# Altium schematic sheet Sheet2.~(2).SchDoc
size A3
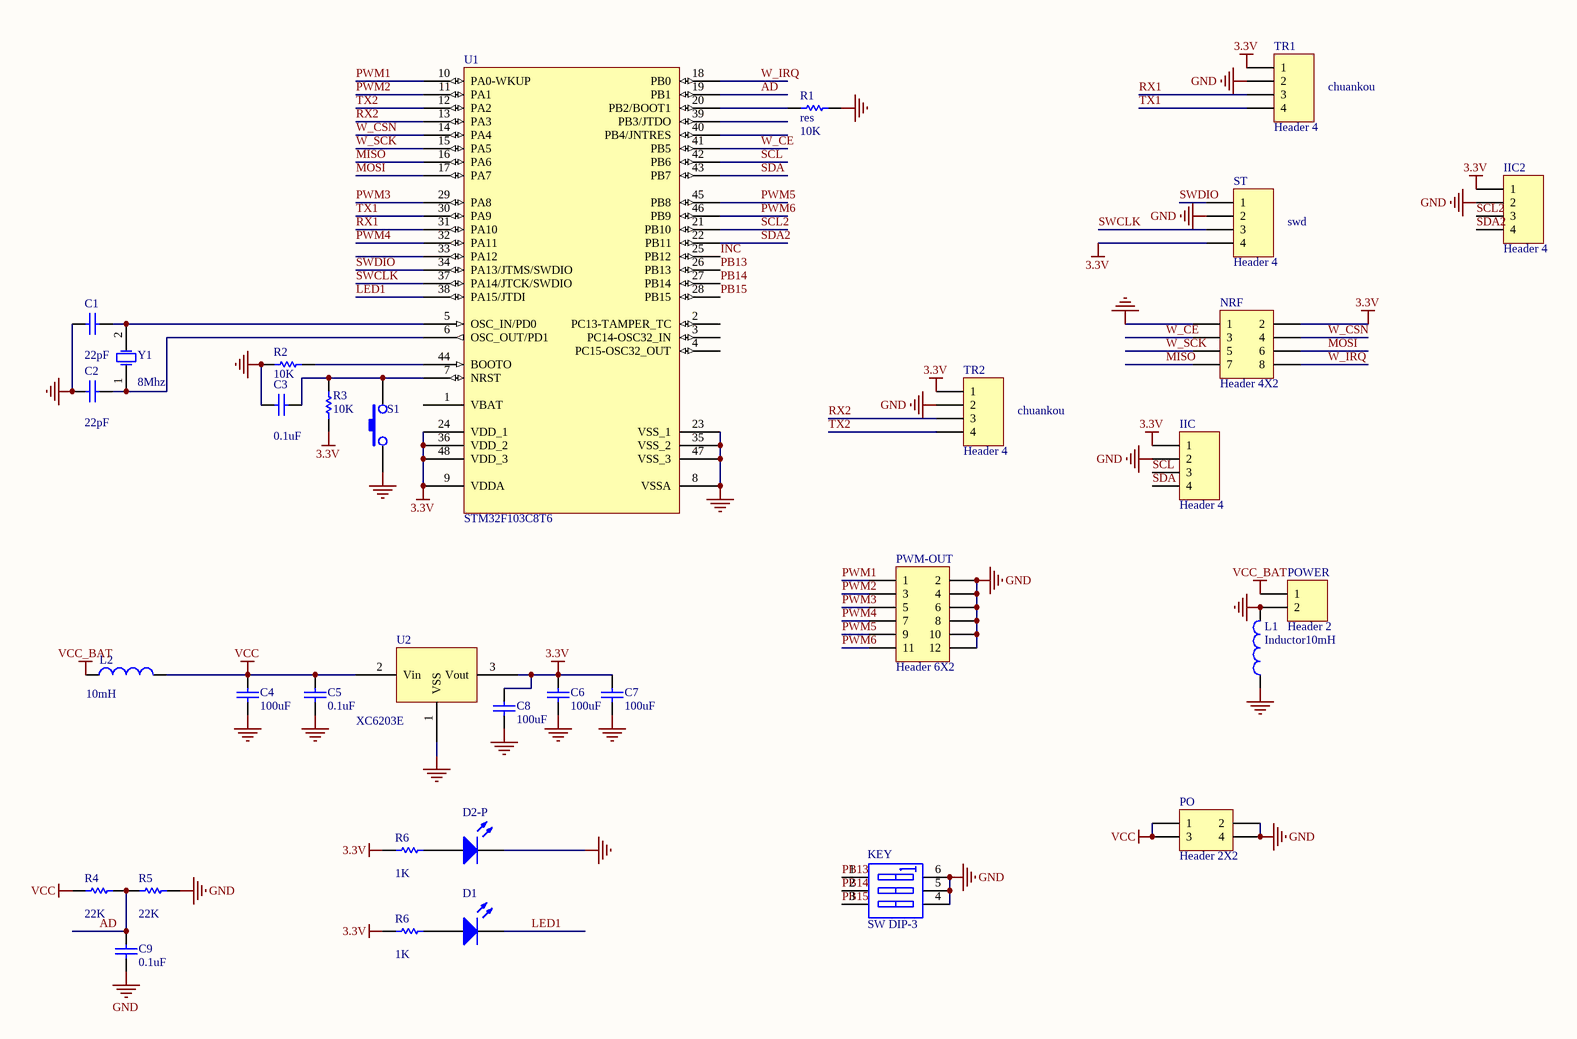
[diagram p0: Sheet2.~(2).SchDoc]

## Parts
(Parts that share a designator on the sheet are numbered #1, #2 ... from top to bottom, then left to right.)
C1  value 22pF  [0603]  (hidden comment: cap)
C2  value 22pF  [0603]  (hidden comment: cap)
C3  value 0.1uF  [0603]  (hidden comment: cap)
C4  value 100uF  [0603]  (hidden comment: cap)
C5  value 0.1uF  [0603]  (hidden comment: cap)
C6  value 100uF  [0603]  (hidden comment: cap)
C7  value 100uF  [0603]  (hidden comment: cap)
C8  value 100uF  [0603]  (hidden comment: cap)
C9  value 0.1uF  [0603]  (hidden comment: cap)
D1  LED0  [0805]  (value not drawn)
D2-P  LED0  [0805]  (value not drawn)
IIC  Header 4  [HDR1X4]
IIC2  Header 4  [HDR1X4]
KEY  SW DIP-3
L1  Inductor10mH  [0805]
L2  value 10mH  [0805]  (hidden comment: Inductor)
NRF  Header 4X2  [HDR2X4]
PO  Header 2X2  [HDR2X2]
POWER  Header 2  [HDR1X2]
PWM-OUT  Header 6X2  [HDR2X6]
R1  res  res: 10K  [0603]
R2  res: 10K  [0603]  (hidden comment: res)
R3  res: 10K  [0603]  (hidden comment: res)
R4  res: 22K  [0603]  (hidden comment: res)
R5  res: 22K  [0603]  (hidden comment: res)
R6#1  res: 1K  [0603]  (hidden comment: res)
R6#2  res: 1K  [0603]  (hidden comment: res)
S1  (no value)
ST  Header 4  [HDR1X4]
TR1  Header 4  [HDR1X4]
TR2  Header 4  [HDR1X4]
U1  STM32F103C8T6  [LQFP48S]
U2  XC6203E  [SOT-89]
Y1  5032xtal  [XTAL]  (value not drawn)

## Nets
3.3V: C6.2 C7.2 C8.2 IIC.1 IIC2.1 NRF.2 R3.1 R6#1.1 R6#2.1 ST.4 TR1.1 TR2.1 U1.9(VDDA) U1.24(VDD_1) U1.36(VDD_2) U1.48(VDD_3) U2.3(Vout)
GND: C1.1 C2.1 C3.1 C4.1 C5.1 C6.1 C7.1 C8.1 C9.1 D2-P.2(K) IIC.2 IIC2.2 KEY.4(B3) KEY.5(B2) KEY.6(B1) L1.1 L1.2 NRF.1 PO.2 PO.4 POWER.2 PWM-OUT.2 PWM-OUT.4 PWM-OUT.6 PWM-OUT.8 PWM-OUT.10 PWM-OUT.12 R1.2 R2.1 R5.2 S1.1 ST.2 TR1.2 TR2.2 U1.8(VSSA) U1.23(VSS_1) U1.35(VSS_2) U1.47(VSS_3) U2.1(VSS)
VCC: C4.2 C5.2 L2.2 PO.1 PO.3 R4.1 U2.2(Vin)
VCC_BAT: L2.1 POWER.1
AD: C9.2 R4.2 R5.1 U1.19(PB1)
INC: U1.25(PB12)
LED1: D1.2(K) U1.38(PA15/JTDI)
MISO: NRF.7 U1.16(PA6)
MOSI: NRF.6 U1.17(PA7)
PB13: KEY.1(A1) U1.26(PB13)
PB14: KEY.2(A2) U1.27(PB14)
PB15: KEY.3(A3) U1.28(PB15)
PWM1: PWM-OUT.1 U1.10(PA0-WKUP)
PWM2: PWM-OUT.3 U1.11(PA1)
PWM3: PWM-OUT.5 U1.29(PA8)
PWM4: PWM-OUT.7 U1.32(PA11)
PWM5: PWM-OUT.9 U1.45(PB8)
PWM6: PWM-OUT.11 U1.46(PB9)
RX1: TR1.3 U1.31(PA10)
RX2: TR2.3 U1.13(PA3)
SCL: IIC.3 U1.42(PB6)
SCL2: IIC2.3 U1.21(PB10)
SDA: IIC.4 U1.43(PB7)
SDA2: IIC2.4 U1.22(PB11)
SWCLK: ST.3 U1.37(PA14/JTCK/SWDIO)
SWDIO: ST.1 U1.34(PA13/JTMS/SWDIO)
TX1: TR1.4 U1.30(PA9)
TX2: TR2.4 U1.12(PA2)
W_CE: NRF.3 U1.41(PB5)
W_CSN: NRF.4 U1.14(PA4)
W_IRQ: NRF.8 U1.18(PB0)
W_SCK: NRF.5 U1.15(PA5)
NetC1_2: C1.2 U1.5(OSC_IN/PD0) Y1.2(OSC2)
NetC2_2: C2.2 U1.6(OSC_OUT/PD1) Y1.1(OSC1)
NetC3_2: C3.2 R3.2 S1.2 U1.7(NRST)
NetD1_1: D1.1(A) R6#2.2
NetD2-P_1: D2-P.1(A) R6#1.2
NetR1_1: R1.1 U1.20(PB2/BOOT1)
NetR2_2: R2.2 U1.44(BOOTO)

Not connected (* = marked no-connect by the designer): U1 1(VBAT) 2(PC13-TAMPER_TC) 3(PC14-OSC32_IN) 4(PC15-OSC32_OUT) 33(PA12) 39(PB3/JTDO) 40(PB4/JNTRES)

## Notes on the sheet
- chuankou
- swd

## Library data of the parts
D1 D2-P = LED0: Typical INFRARED GaAs LED
IIC IIC2 ST TR1 TR2 = Header 4: Header, 4-Pin
KEY = SW DIP-3: DIP Switch
L1 = Inductor
NRF = Header 4X2: Header, 4-Pin, Dual row
PO = Header 2X2: Header, 2-Pin, Dual row
POWER = Header 2: Header, 2-Pin
PWM-OUT = Header 6X2: Header, 6-Pin, Dual row
S1 = 微动开关
U2 = XC6203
